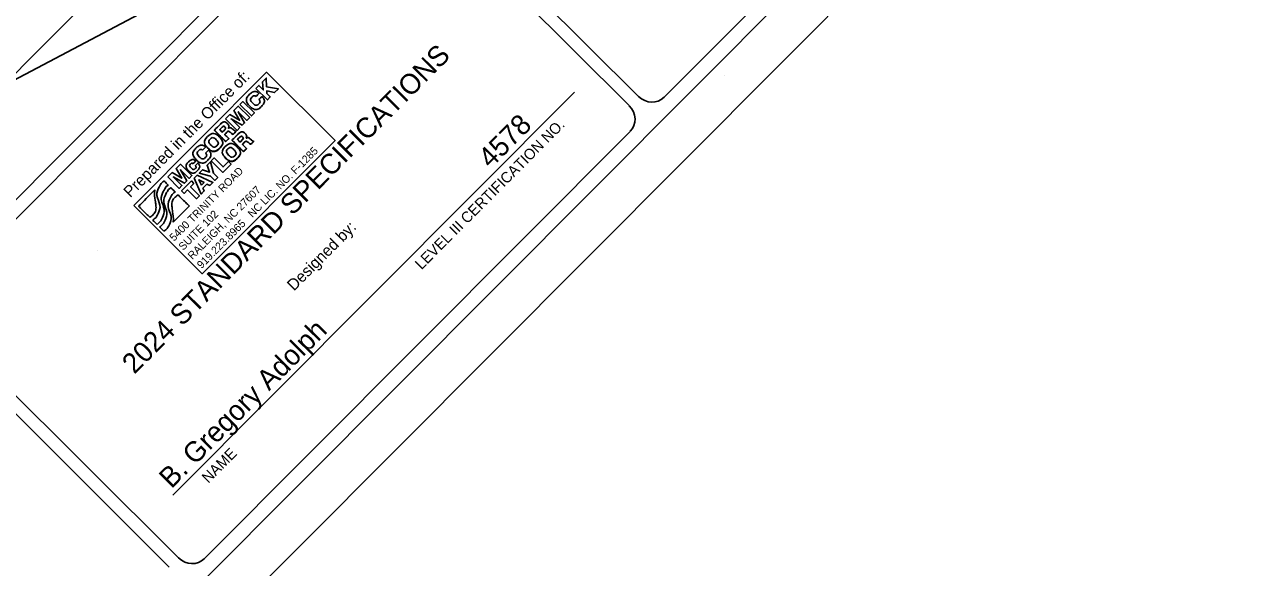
# Model space of a CAD drawing. Extents: x 1484932 to 1495672, y 495497 to 506262.
# Drawn here: x 1488841 to 1490835, y 497486 to 498363 of the extents above; entities that cross this region are included whole.
import ezdxf

# ---------------------------------------------------------------- set-up
doc = ezdxf.new("R2010")
doc.units = 0
for name, color, linetype in [('Old_Level_18', 7, 'Continuous'), ('Prop DSN White Annotation Label', 7, 'Continuous'), ('Scratch_Level_4', 7, 'Continuous'), ('Sheet Plot Border Outside CELL', 7, 'Continuous')]:
    doc.layers.add(name, color=color, linetype=linetype)

msp = doc.modelspace()

# ---------------------------------------------------------------- linework, layer by layer
at = {"layer": 'Old_Level_18'}
for p, q in [((1487209.6, 496457.5), (1490254.5, 499515.1)), ((1490697.4, 499073.3), (1489873.5, 498246)), ((1489448.3, 498629.2), (1489831.9, 498247.1)), ((1488703, 497925.4), (1489391.5, 498616.8)), ((1489817.2, 498232.4), (1489432.7, 498615.3)), ((1489433.6, 498614.5), (1489817.2, 498232.4)), ((1489214, 498260), (1489218.8, 498264.9)), ((1489218.8, 498264.9), (1489225.9, 498257.8)), ((1489224.9, 498271), (1489230.8, 498277)), ((1489225.9, 498257.8), (1489224.9, 498271)), ((1489230.8, 498277), (1489231.3, 498262.8)), ((1489079.8, 497602.7), (1489728.6, 498254.2)), ((1489232.5, 498241.6), (1489214, 498260)), ((1489231.3, 498262.8), (1489250.3, 498259.4)), ((1489244.3, 498253.4), (1489231.5, 498256.1)), ((1489231.5, 498256.1), (1489231.6, 498252.1)), ((1489231.6, 498252.1), (1489237.3, 498246.4)), ((1489237.3, 498246.4), (1489232.5, 498241.6)), ((1489250.3, 498259.4), (1489244.3, 498253.4)), ((1489178.5, 498224.4), (1489185.5, 498231.5)), ((1489187.6, 498208.8), (1489178.5, 498224.4)), ((1489185.5, 498231.5), (1489204.1, 498213)), ((1489188.2, 498234.2), (1489193.1, 498239)), ((1489206.8, 498215.7), (1489188.2, 498234.2)), ((1489193.1, 498239), (1489211.6, 498220.5)), ((1489164.9, 498210.8), (1489172, 498217.9)), ((1489183.5, 498192.3), (1489164.9, 498210.8)), ((1489172, 498217.9), (1489187.6, 498208.8)), ((1489174, 498210.9), (1489173.9, 498210.9)), ((1489173.9, 498210.9), (1489188, 498196.9)), ((1489192, 498200.8), (1489174, 498210.9)), ((1489185.5, 498222.5), (1489185.4, 498222.4)), ((1489185.4, 498222.4), (1489195.6, 498204.5)), ((1489199.6, 498208.5), (1489185.5, 498222.5)), ((1489187.6, 498208.8), (1489187.6, 498208.8)), ((1489195.6, 498204.5), (1489192, 498200.8)), ((1489204.1, 498213), (1489199.6, 498208.5)), ((1489211.6, 498220.5), (1489206.8, 498215.7)), ((1489818.5, 498190.7), (1489130.4, 497499.8)), ((1489169.7, 498195.9), (1489169.8, 498195.8)), ((1489181.9, 498190.7), (1489177.1, 498185.9)), ((1489188, 498196.9), (1489183.5, 498192.3)), ((1489198.4, 498179.8), (1489198.4, 498179.7)), ((1489210.5, 498174.6), (1489205.7, 498169.9)), ((1489141.9, 498142.9), (1489146.7, 498147.7)), ((1489146.7, 498147.7), (1489161.1, 498133.4)), ((1489071.5, 498117), (1489078.6, 498124.1)), ((1489078.6, 498124.1), (1489094.2, 498115)), ((1489085, 498130.5), (1489092.1, 498137.7)), ((1489094.2, 498115), (1489085, 498130.5)), ((1489092.1, 498128.7), (1489092, 498128.6)), ((1489092, 498128.6), (1489102.2, 498110.7)), ((1489092.1, 498137.7), (1489110.7, 498119.2)), ((1489106.2, 498114.6), (1489092.1, 498128.7)), ((1489122.4, 498123.3), (1489127.8, 498128.7)), ((1489127.8, 498128.7), (1489139.1, 498124.9)), ((1489135.2, 498136.1), (1489140.7, 498141.6)), ((1489139.1, 498124.9), (1489135.2, 498136.1)), ((1489140.7, 498141.6), (1489145.6, 498123.2)), ((1489160.5, 498124.4), (1489141.9, 498142.9)), ((1489173.9, 498137.9), (1489160.5, 498124.4)), ((1489161.1, 498133.4), (1489169.8, 498142)), ((1489169.8, 498142), (1489173.9, 498137.9)), ((1489090.1, 498098.5), (1489071.5, 498117)), ((1489080.6, 498117.1), (1489080.5, 498117.1)), ((1489080.5, 498117.1), (1489094.6, 498103)), ((1489098.5, 498107), (1489080.6, 498117.1)), ((1489093.9, 498094.7), (1489109.8, 498110.6)), ((1489094.2, 498115), (1489094.2, 498115)), ((1489102.2, 498110.7), (1489098.5, 498107)), ((1489110.7, 498119.2), (1489106.2, 498114.6)), ((1489113.9, 498106.4), (1489108.4, 498100.9)), ((1489109.8, 498110.6), (1489113.9, 498106.4)), ((1489114.1, 498114.9), (1489119, 498119.8)), ((1489125.7, 498089.5), (1489114.1, 498114.9)), ((1489119, 498119.8), (1489144.5, 498108.3)), ((1489121.7, 498112.3), (1489121.6, 498112.2)), ((1489121.6, 498112.2), (1489126, 498103.6)), ((1489130.2, 498107.9), (1489121.7, 498112.3)), ((1489140.8, 498118.4), (1489122.4, 498123.3)), ((1489126, 498103.6), (1489130.2, 498107.9)), ((1489135, 498105.4), (1489128.5, 498099)), ((1489139.4, 498103.3), (1489135, 498105.4)), ((1489144.5, 498108.3), (1489139.4, 498103.3)), ((1489147.7, 498111.5), (1489140.8, 498118.4)), ((1489145.6, 498123.2), (1489152.5, 498116.4)), ((1489152.5, 498116.4), (1489147.7, 498111.5)), ((1489094.6, 498103), (1489090.1, 498098.5)), ((1489098.1, 498090.5), (1489093.9, 498094.7)), ((1489103.6, 498096.1), (1489098.1, 498090.5)), ((1489118, 498081.7), (1489103.6, 498096.1)), ((1489108.4, 498100.9), (1489122.8, 498086.6)), ((1489122.8, 498086.6), (1489118, 498081.7)), ((1489130.7, 498094.5), (1489125.7, 498089.5)), ((1489128.5, 498099), (1489130.7, 498094.5)), ((1488958.7, 497998.7), (1488958.7, 497998.7)), ((1488690.9, 497868.6), (1489074.1, 497486.1)), ((1488704.7, 497884.2), (1489089.2, 497501.3))]:
    msp.add_line(p, q, dxfattribs=at)
for points in [[(1487537.4, 495866.7), (1490713.3, 499055.9)], [(1489214, 498260), (1489218.8, 498264.9), (1489225.9, 498257.8), (1489224.9, 498271), (1489230.8, 498277), (1489231.3, 498262.8), (1489250.3, 498259.4), (1489244.3, 498253.4), (1489231.5, 498256.1), (1489231.6, 498252.1), (1489237.3, 498246.4), (1489232.5, 498241.6), (1489214, 498260)], [(1489164.9, 498210.8), (1489172, 498217.9), (1489187.6, 498208.8), (1489187.6, 498208.8), (1489178.5, 498224.4), (1489185.5, 498231.5), (1489204.1, 498213), (1489199.6, 498208.5), (1489185.5, 498222.5), (1489185.4, 498222.4), (1489195.6, 498204.5), (1489192, 498200.8), (1489174, 498210.9), (1489173.9, 498210.9), (1489188, 498196.9), (1489183.5, 498192.3), (1489164.9, 498210.8)], [(1489188.2, 498234.2), (1489193.1, 498239), (1489211.6, 498220.5), (1489206.8, 498215.7), (1489188.2, 498234.2)], [(1489167.1, 498189.4), (1489163.5, 498185.7), (1489170.3, 498179), (1489165.4, 498174.2), (1489146.9, 498192.7), (1489156.3, 498202.1)], [(1489159.4, 498197.5), (1489155.6, 498193.6), (1489159.7, 498189.5), (1489163.8, 498193.5)], [(1489195.8, 498173.3), (1489192.1, 498169.7), (1489198.9, 498162.9), (1489194, 498158.1), (1489175.5, 498176.6), (1489184.9, 498186)], [(1489188, 498181.4), (1489184.2, 498177.6), (1489188.4, 498173.4), (1489192.4, 498177.5)], [(1489141.9, 498142.9), (1489146.7, 498147.7), (1489161.1, 498133.4), (1489169.8, 498142), (1489173.9, 498137.9), (1489160.5, 498124.4), (1489141.9, 498142.9)], [(1489071.5, 498117), (1489078.6, 498124.1), (1489094.2, 498115), (1489094.2, 498115), (1489085, 498130.5), (1489092.1, 498137.7), (1489110.7, 498119.2), (1489106.2, 498114.6), (1489092.1, 498128.7), (1489092, 498128.6), (1489102.2, 498110.7), (1489098.5, 498107), (1489080.6, 498117.1), (1489080.5, 498117.1), (1489094.6, 498103), (1489090.1, 498098.5), (1489071.5, 498117)], [(1489145.6, 498123.2), (1489152.5, 498116.4), (1489147.7, 498111.5), (1489140.8, 498118.4), (1489122.4, 498123.3), (1489127.8, 498128.7), (1489139.1, 498124.9), (1489135.2, 498136.1), (1489140.7, 498141.6), (1489145.6, 498123.2)], [(1489113.9, 498106.4), (1489108.4, 498100.9), (1489122.8, 498086.6), (1489118, 498081.7), (1489103.6, 498096.1), (1489098.1, 498090.5), (1489093.9, 498094.7), (1489109.8, 498110.6), (1489113.9, 498106.4)], [(1489114.1, 498114.9), (1489119, 498119.8), (1489144.5, 498108.3), (1489139.4, 498103.3), (1489135, 498105.4), (1489128.5, 498099), (1489130.7, 498094.5), (1489125.7, 498089.5), (1489114.1, 498114.9)], [(1489126, 498103.6), (1489130.2, 498107.9), (1489121.7, 498112.3), (1489121.6, 498112.2), (1489126, 498103.6)]]:
    msp.add_lwpolyline(points, dxfattribs=at)
msp.add_lwpolyline([(1489016.6, 498071), (1489231.1, 498286.4), (1489341.9, 498176.1), (1489127.4, 497960.7)], close=True, dxfattribs=at)
for centre, major_axis, start_param, end_param in [((1489851.9, 498267.1), (21.4, -21.3), 4.712389, 6.283185), ((1489797.3, 498212.3), (-21.4, 21.3), 3.141593, 4.712389), ((1489109, 497521.2), (21.4, -21.3), 4.712389, 6.283185)]:
    msp.add_ellipse(centre, major_axis=major_axis, ratio=0.927398, start_param=start_param, end_param=end_param, dxfattribs=at)
for points in [[(1489214.3, 498247.1), (1489212.1, 498248.7), (1489209.7, 498248.2), (1489207.7, 498246.2), (1489204.6, 498243), (1489206.1, 498239.1), (1489208.9, 498236.4), (1489211.6, 498233.6), (1489215.6, 498232.1), (1489218.7, 498235.2), (1489220.9, 498237.5), (1489220.9, 498240), (1489219, 498242.4), (1489219, 498242.4), (1489223.8, 498247.2), (1489223.8, 498247.2), (1489228.3, 498242.2), (1489227.6, 498235.9), (1489223, 498231.2), (1489217.4, 498225.5), (1489209.5, 498226.2), (1489204.1, 498231.5), (1489198.7, 498236.9), (1489198, 498244.8), (1489203.6, 498250.4), (1489207.6, 498254.4), (1489214.5, 498256.2), (1489219.1, 498251.9), (1489219.1, 498251.9), (1489214.3, 498247.1), (1489214.3, 498247.1)], [(1489214.3, 498247.1), (1489212.1, 498248.7), (1489209.7, 498248.2), (1489207.7, 498246.2), (1489204.6, 498243), (1489206.1, 498239.1), (1489208.9, 498236.4), (1489211.6, 498233.6), (1489215.6, 498232.1), (1489218.7, 498235.2), (1489220.9, 498237.5), (1489220.9, 498240), (1489219, 498242.4), (1489219, 498242.4), (1489223.8, 498247.2), (1489223.8, 498247.2), (1489228.3, 498242.2), (1489227.6, 498235.9), (1489223, 498231.2), (1489217.4, 498225.5), (1489209.5, 498226.2), (1489204.1, 498231.5), (1489198.7, 498236.9), (1489198, 498244.8), (1489203.6, 498250.4), (1489207.6, 498254.4), (1489214.5, 498256.2), (1489219.1, 498251.9), (1489219.1, 498251.9), (1489214.3, 498247.1), (1489214.3, 498247.1)], [(1489146.9, 498192.7), (1489146.9, 498192.7), (1489156.3, 498202.1), (1489156.3, 498202.1), (1489159.6, 498205.4), (1489164.3, 498207.1), (1489168, 498203.4), (1489170, 498201.4), (1489170.9, 498198.6), (1489169.7, 498195.9), (1489169.7, 498195.9), (1489169.8, 498195.8), (1489169.8, 498195.8), (1489172.2, 498197.3), (1489175, 498195.7), (1489176.9, 498194.1), (1489177.8, 498193.4), (1489180.6, 498190.7), (1489181.9, 498190.7), (1489181.9, 498190.7), (1489177.1, 498185.9), (1489177.1, 498185.9), (1489176.1, 498186.1), (1489174.2, 498187.9), (1489173.6, 498188.3), (1489171.6, 498190.1), (1489169.4, 498191.7), (1489167.1, 498189.4), (1489167.1, 498189.4), (1489163.5, 498185.7), (1489163.5, 498185.7), (1489163.5, 498185.7), (1489170.3, 498179), (1489170.3, 498179), (1489170.3, 498179), (1489165.4, 498174.2), (1489165.4, 498174.2), (1489165.4, 498174.2), (1489146.9, 498192.7), (1489146.9, 498192.7)], [(1489156.3, 498202.1), (1489159.6, 498205.4), (1489164.3, 498207.1), (1489168, 498203.4), (1489170, 498201.4), (1489170.9, 498198.6), (1489169.7, 498195.9)], [(1489135.9, 498182.5), (1489141.8, 498188.3), (1489149.3, 498187.3), (1489154.7, 498182), (1489160.1, 498176.6), (1489161.1, 498169), (1489155.3, 498163.2), (1489149.5, 498157.4), (1489141.9, 498158.3), (1489136.5, 498163.7), (1489131.1, 498169), (1489130.1, 498176.6), (1489135.9, 498182.5)], [(1489135.9, 498182.5), (1489141.8, 498188.3), (1489149.3, 498187.3), (1489154.7, 498182), (1489160.1, 498176.6), (1489161.1, 498169), (1489155.3, 498163.2), (1489154.5, 498162.4), (1489153.7, 498161.7), (1489152.8, 498161.2)], [(1489159.7, 498189.5), (1489159.7, 498189.5), (1489163.8, 498193.5), (1489163.8, 498193.5), (1489165.2, 498195), (1489165.2, 498196.5), (1489163.8, 498197.9), (1489162.5, 498199.3), (1489160.7, 498198.8), (1489159.4, 498197.5), (1489159.4, 498197.5), (1489155.6, 498193.6), (1489155.6, 498193.6), (1489155.6, 498193.6), (1489159.7, 498189.5), (1489159.7, 498189.5)], [(1489163.8, 498193.5), (1489165.2, 498195), (1489165.2, 498196.5), (1489163.8, 498197.9), (1489162.5, 498199.3), (1489160.7, 498198.8), (1489159.4, 498197.5)], [(1489177.1, 498185.9), (1489176.1, 498186.1), (1489174.2, 498187.9), (1489173.6, 498188.3), (1489171.6, 498190.1), (1489169.4, 498191.7), (1489167.1, 498189.4)], [(1489169.8, 498195.8), (1489172.2, 498197.3), (1489175, 498195.7), (1489176.9, 498194.1), (1489177.8, 498193.4), (1489180.6, 498190.7), (1489181.9, 498190.7)], [(1489175.5, 498176.6), (1489175.5, 498176.6), (1489184.9, 498186), (1489184.9, 498186), (1489188.2, 498189.3), (1489192.9, 498191.1), (1489196.6, 498187.3), (1489198.6, 498185.3), (1489199.5, 498182.5), (1489198.4, 498179.8), (1489198.4, 498179.8), (1489198.4, 498179.7), (1489198.4, 498179.7), (1489200.8, 498181.3), (1489203.6, 498179.6), (1489205.5, 498178), (1489206.4, 498177.3), (1489209.2, 498174.7), (1489210.5, 498174.6), (1489210.5, 498174.6), (1489205.7, 498169.9), (1489205.7, 498169.9), (1489204.7, 498170.1), (1489202.8, 498171.8), (1489202.2, 498172.3), (1489200.2, 498174), (1489198, 498175.6), (1489195.8, 498173.3), (1489195.8, 498173.3), (1489192.1, 498169.7), (1489192.1, 498169.7), (1489192.1, 498169.7), (1489198.9, 498162.9), (1489198.9, 498162.9), (1489198.9, 498162.9), (1489194, 498158.1), (1489194, 498158.1), (1489194, 498158.1), (1489175.5, 498176.6), (1489175.5, 498176.6)], [(1489184.9, 498186), (1489188.2, 498189.3), (1489192.9, 498191.1), (1489196.6, 498187.3), (1489198.6, 498185.3), (1489199.5, 498182.5), (1489198.4, 498179.8)], [(1489127.9, 498160.4), (1489125.8, 498162), (1489123.4, 498161.5), (1489121.3, 498159.5), (1489118.2, 498156.4), (1489119.8, 498152.4), (1489122.6, 498149.7), (1489125.3, 498146.9), (1489129.3, 498145.4), (1489132.4, 498148.5), (1489134.6, 498150.8), (1489134.6, 498153.4), (1489132.7, 498155.7), (1489132.7, 498155.7), (1489137.5, 498160.5), (1489137.5, 498160.5), (1489142, 498155.5), (1489141.3, 498149.2), (1489136.6, 498144.5), (1489131, 498138.8), (1489123.1, 498139.5), (1489117.7, 498144.8), (1489112.4, 498150.2), (1489111.7, 498158.1), (1489117.3, 498163.7), (1489121.3, 498167.7), (1489128.1, 498169.5), (1489132.7, 498165.2), (1489132.7, 498165.2), (1489127.9, 498160.4), (1489127.9, 498160.4)], [(1489127.9, 498160.4), (1489125.8, 498162), (1489123.4, 498161.5), (1489121.3, 498159.5), (1489118.2, 498156.4), (1489119.8, 498152.4), (1489122.6, 498149.7), (1489125.3, 498146.9), (1489129.3, 498145.4), (1489132.4, 498148.5), (1489134.6, 498150.8), (1489134.6, 498153.4), (1489132.7, 498155.7), (1489132.7, 498155.7), (1489137.5, 498160.5), (1489137.5, 498160.5), (1489142, 498155.5), (1489141.3, 498149.2), (1489136.6, 498144.5), (1489131, 498138.8), (1489123.1, 498139.5), (1489117.7, 498144.8), (1489112.4, 498150.2), (1489111.7, 498158.1), (1489117.3, 498163.7), (1489121.3, 498167.7), (1489128.1, 498169.5), (1489132.7, 498165.2), (1489132.7, 498165.2), (1489127.9, 498160.4), (1489127.9, 498160.4)], [(1489152.8, 498161.2), (1489147.4, 498157.7), (1489141.2, 498159.1), (1489136.5, 498163.7), (1489131.1, 498169), (1489130.1, 498176.6), (1489135.9, 498182.5)], [(1489151.1, 498167.3), (1489154.2, 498170.5), (1489152.7, 498174.4), (1489149.9, 498177.1), (1489147.2, 498179.9), (1489143.2, 498181.4), (1489140.1, 498178.3), (1489137, 498175.2), (1489138.6, 498171.3), (1489141.3, 498168.5), (1489144.1, 498165.8), (1489148, 498164.2), (1489151.1, 498167.3)], [(1489151.1, 498167.3), (1489154.2, 498170.5), (1489152.7, 498174.4), (1489149.9, 498177.1), (1489147.2, 498179.9), (1489143.2, 498181.4), (1489140.1, 498178.3), (1489137, 498175.2), (1489138.6, 498171.3), (1489141.3, 498168.5), (1489144.1, 498165.8), (1489148, 498164.2), (1489151.1, 498167.3)], [(1489164.6, 498166.4), (1489170.4, 498172.3), (1489178, 498171.3), (1489183.4, 498165.9), (1489188.7, 498160.6), (1489189.7, 498153), (1489183.9, 498147.2), (1489178.1, 498141.3), (1489170.5, 498142.3), (1489165.1, 498147.6), (1489159.8, 498153), (1489158.8, 498160.6), (1489164.6, 498166.4)], [(1489181.4, 498145.1), (1489176.1, 498141.7), (1489169.8, 498143), (1489165.1, 498147.6), (1489159.8, 498153), (1489158.8, 498160.6), (1489164.6, 498166.4)], [(1489164.6, 498166.4), (1489170.4, 498172.3), (1489178, 498171.3), (1489183.4, 498165.9), (1489188.7, 498160.6), (1489189.7, 498153), (1489183.9, 498147.2), (1489183.1, 498146.4), (1489182.3, 498145.7), (1489181.4, 498145.1)], [(1489179.8, 498151.3), (1489182.9, 498154.4), (1489181.3, 498158.4), (1489178.6, 498161.1), (1489175.8, 498163.8), (1489171.9, 498165.4), (1489168.7, 498162.3), (1489165.6, 498159.2), (1489167.2, 498155.2), (1489170, 498152.5), (1489172.7, 498149.7), (1489176.7, 498148.2), (1489179.8, 498151.3)], [(1489179.8, 498151.3), (1489182.9, 498154.4), (1489181.3, 498158.4), (1489178.6, 498161.1), (1489175.8, 498163.8), (1489171.9, 498165.4), (1489168.7, 498162.3), (1489165.6, 498159.2), (1489167.2, 498155.2), (1489170, 498152.5), (1489172.7, 498149.7), (1489176.7, 498148.2), (1489179.8, 498151.3)], [(1489188.4, 498173.4), (1489188.4, 498173.4), (1489192.4, 498177.5), (1489192.4, 498177.5), (1489193.8, 498178.9), (1489193.8, 498180.5), (1489192.4, 498181.9), (1489191.1, 498183.2), (1489189.4, 498182.8), (1489188, 498181.4), (1489188, 498181.4), (1489184.2, 498177.6), (1489184.2, 498177.6), (1489184.2, 498177.6), (1489188.4, 498173.4), (1489188.4, 498173.4)], [(1489192.4, 498177.5), (1489193.8, 498178.9), (1489193.8, 498180.5), (1489192.4, 498181.9), (1489191.1, 498183.2), (1489189.4, 498182.8), (1489188, 498181.4)], [(1489205.7, 498169.9), (1489204.7, 498170.1), (1489202.8, 498171.8), (1489202.2, 498172.3), (1489200.2, 498174), (1489198, 498175.6), (1489195.8, 498173.3)], [(1489198.4, 498179.7), (1489200.8, 498181.3), (1489203.6, 498179.6), (1489205.5, 498178), (1489206.4, 498177.3), (1489209.2, 498174.7), (1489210.5, 498174.6)], [(1489112.8, 498138.5), (1489111.7, 498139.6), (1489109.9, 498139.4), (1489108.7, 498138.2), (1489106.3, 498135.8), (1489108, 498133.3), (1489109.9, 498131.4), (1489111.6, 498129.7), (1489114.2, 498128.7), (1489116, 498130.5), (1489117.6, 498132.1), (1489117.4, 498133.7), (1489116.2, 498135.4), (1489116.2, 498135.4), (1489120.5, 498139.6), (1489120.5, 498139.6), (1489123.7, 498135.7), (1489123, 498130.8), (1489119.4, 498127.2), (1489115.4, 498123.1), (1489109.6, 498122.9), (1489105.5, 498127), (1489101.2, 498131.3), (1489100.8, 498137.1), (1489105.2, 498141.4), (1489108.5, 498144.8), (1489113.2, 498146), (1489117.1, 498142.7), (1489117.1, 498142.7), (1489112.8, 498138.5), (1489112.8, 498138.5)], [(1489112.8, 498138.5), (1489111.7, 498139.6), (1489109.9, 498139.4), (1489108.7, 498138.2), (1489106.3, 498135.8), (1489108, 498133.3), (1489109.9, 498131.4), (1489111.6, 498129.7), (1489114.2, 498128.7), (1489116, 498130.5), (1489117.6, 498132.1), (1489117.4, 498133.7), (1489116.2, 498135.4), (1489116.2, 498135.4), (1489120.5, 498139.6), (1489120.5, 498139.6), (1489123.7, 498135.7), (1489123, 498130.8), (1489119.4, 498127.2), (1489115.4, 498123.1), (1489109.6, 498122.9), (1489105.5, 498127), (1489101.2, 498131.3), (1489100.8, 498137.1), (1489105.2, 498141.4), (1489108.5, 498144.8), (1489113.2, 498146), (1489117.1, 498142.7), (1489117.1, 498142.7), (1489112.8, 498138.5), (1489112.8, 498138.5)], [(1489054.3, 498040.3), (1489056.7, 498042.7), (1489059.5, 498044.2), (1489062.6, 498050.1), (1489068.7, 498063.9), (1489058.1, 498080.9), (1489064.9, 498094.7), (1489068.8, 498101.7), (1489072.5, 498103.8), (1489072.5, 498103.8), (1489072.5, 498103.8), (1489065.7, 498110.6), (1489065.7, 498110.6), (1489065.7, 498110.6), (1489061.9, 498108.5), (1489058, 498101.6), (1489051.2, 498087.7), (1489061.8, 498070.7), (1489055.7, 498056.9), (1489052.6, 498051), (1489049.8, 498049.5), (1489047.5, 498047.1), (1489047.5, 498047.1), (1489054.3, 498040.3), (1489054.3, 498040.3)], [(1489054.3, 498040.3), (1489056.7, 498042.7), (1489059.5, 498044.2), (1489062.6, 498050.1), (1489068.7, 498063.9), (1489058.1, 498080.9), (1489064.9, 498094.7), (1489068.8, 498101.7), (1489072.5, 498103.8), (1489072.5, 498103.8), (1489072.5, 498103.8), (1489065.7, 498110.6), (1489065.7, 498110.6), (1489065.7, 498110.6), (1489061.9, 498108.5), (1489058, 498101.6), (1489051.2, 498087.7), (1489061.8, 498070.7), (1489055.7, 498056.9), (1489052.6, 498051), (1489049.8, 498049.5), (1489047.5, 498047.1), (1489047.5, 498047.1), (1489054.3, 498040.3), (1489054.3, 498040.3)], [(1489050.7, 498096.2), (1489049.7, 498089.1), (1489051.9, 498077), (1489052.3, 498072.9), (1489053.2, 498062.7), (1489048.9, 498056.5), (1489042.8, 498051.7), (1489042.8, 498051.7), (1489024.6, 498069.9), (1489024.6, 498069.9), (1489024.6, 498069.9), (1489050.7, 498096.2), (1489050.7, 498096.2)], [(1489050.7, 498096.2), (1489049.7, 498089.1), (1489051.9, 498077), (1489052.3, 498072.9), (1489053.2, 498062.7), (1489048.9, 498056.5), (1489042.8, 498051.7), (1489042.8, 498051.7), (1489024.6, 498069.9), (1489024.6, 498069.9), (1489024.6, 498069.9), (1489050.7, 498096.2), (1489050.7, 498096.2)], [(1489065.4, 498029.2), (1489067.8, 498031.6), (1489070.6, 498033.1), (1489073.7, 498039), (1489079.8, 498052.9), (1489069.2, 498069.9), (1489076, 498083.7), (1489079.8, 498090.7), (1489083.6, 498092.7), (1489083.6, 498092.7), (1489083.6, 498092.7), (1489076.8, 498099.6), (1489076.8, 498099.6), (1489076.8, 498099.6), (1489073, 498097.5), (1489069.1, 498090.5), (1489062.3, 498076.7), (1489072.9, 498059.7), (1489066.8, 498045.9), (1489063.7, 498039.9), (1489060.9, 498038.4), (1489058.6, 498036), (1489058.6, 498036), (1489065.4, 498029.2), (1489065.4, 498029.2)], [(1489065.4, 498029.2), (1489067.8, 498031.6), (1489070.6, 498033.1), (1489073.7, 498039), (1489079.8, 498052.9), (1489069.2, 498069.9), (1489076, 498083.7), (1489079.8, 498090.7), (1489083.6, 498092.7), (1489083.6, 498092.7), (1489083.6, 498092.7), (1489076.8, 498099.6), (1489076.8, 498099.6), (1489076.8, 498099.6), (1489073, 498097.5), (1489069.1, 498090.5), (1489062.3, 498076.7), (1489072.9, 498059.7), (1489066.8, 498045.9), (1489063.7, 498039.9), (1489060.9, 498038.4), (1489058.6, 498036), (1489058.6, 498036), (1489065.4, 498029.2), (1489065.4, 498029.2)], [(1489080.2, 498043.8), (1489081.3, 498050.8), (1489079, 498063), (1489078.6, 498067.1), (1489077.7, 498077.3), (1489082.1, 498083.5), (1489088.1, 498088.2), (1489088.1, 498088.2), (1489106.4, 498070.1), (1489106.4, 498070.1), (1489106.4, 498070.1), (1489080.2, 498043.8), (1489080.2, 498043.8)], [(1489080.2, 498043.8), (1489081.3, 498050.8), (1489079, 498063), (1489078.6, 498067.1), (1489077.7, 498077.3), (1489082.1, 498083.5), (1489088.1, 498088.2), (1489088.1, 498088.2), (1489106.4, 498070.1), (1489106.4, 498070.1), (1489106.4, 498070.1), (1489080.2, 498043.8), (1489080.2, 498043.8)]]:
    msp.add_open_spline(points, degree=3, dxfattribs=at)
at = {"layer": 'Prop DSN White Annotation Label'}
msp.add_lwpolyline([(1487208.7, 498608.1), (1488222.1, 499143.2), (1488965.4, 498493.7), (1489025.4, 498380), (1487698.9, 497679.6)], close=True, dxfattribs=at)
at = {"layer": 'Scratch_Level_4'}
msp.add_line((1489971.4, 498280.4), (1489971.4, 498280.4), dxfattribs=at)
msp.add_lwpolyline([(1486969.7, 498427.7), (1489005, 500471.4), (1490008.1, 499472.4), (1487972.8, 497428.7)], close=True, dxfattribs=at)
at = {"layer": 'Sheet Plot Border Outside CELL'}
msp.add_lwpolyline([(1488496.6, 501405.6), (1484931.7, 497825.9), (1487270, 495497.3), (1490834.9, 499077)], close=True, dxfattribs=at)

# ---------------------------------------------------------------- texts
at = {"layer": 'Old_Level_18'}
for s, height, rotation, p in [('2024 STANDARD SPECIFICATIONS', 32.669, 45.1186, (1489017.7, 497797)), ('Prepared in the Office of:', 18.538, 45.1186, (1489011.2, 498082.6)), ('LEVEL III CERTIFICATION NO.', 17.362, 45.1186, (1489481.4, 497966.2)), ('4578', 32.67, 45.1186, (1489593.1, 498129.7)), ('919.223.8965   NC LIC. NO. F-1285', 12.532, 45.1212, (1489126.2, 497968)), ('5400 TRINITY ROAD', 12.532, 45.1212, (1489081.8, 498012.2)), ('RALEIGH, NC 27607', 12.532, 45.1212, (1489111.4, 497982.8)), ('SUITE 102', 12.53, 45.1212, (1489096.6, 497997.5)), ('Designed by:', 18.538, 45.1186, (1489275.6, 497931.9)), ('B. Gregory Adolph', 32.669, 45.1186, (1489077.6, 497612.1)), ('NAME', 17.36, 45.1186, (1489137.2, 497621))]:
    msp.add_text(s, height=height, rotation=rotation, dxfattribs=at).set_placement(p)

doc.saveas('drawing.dxf')
